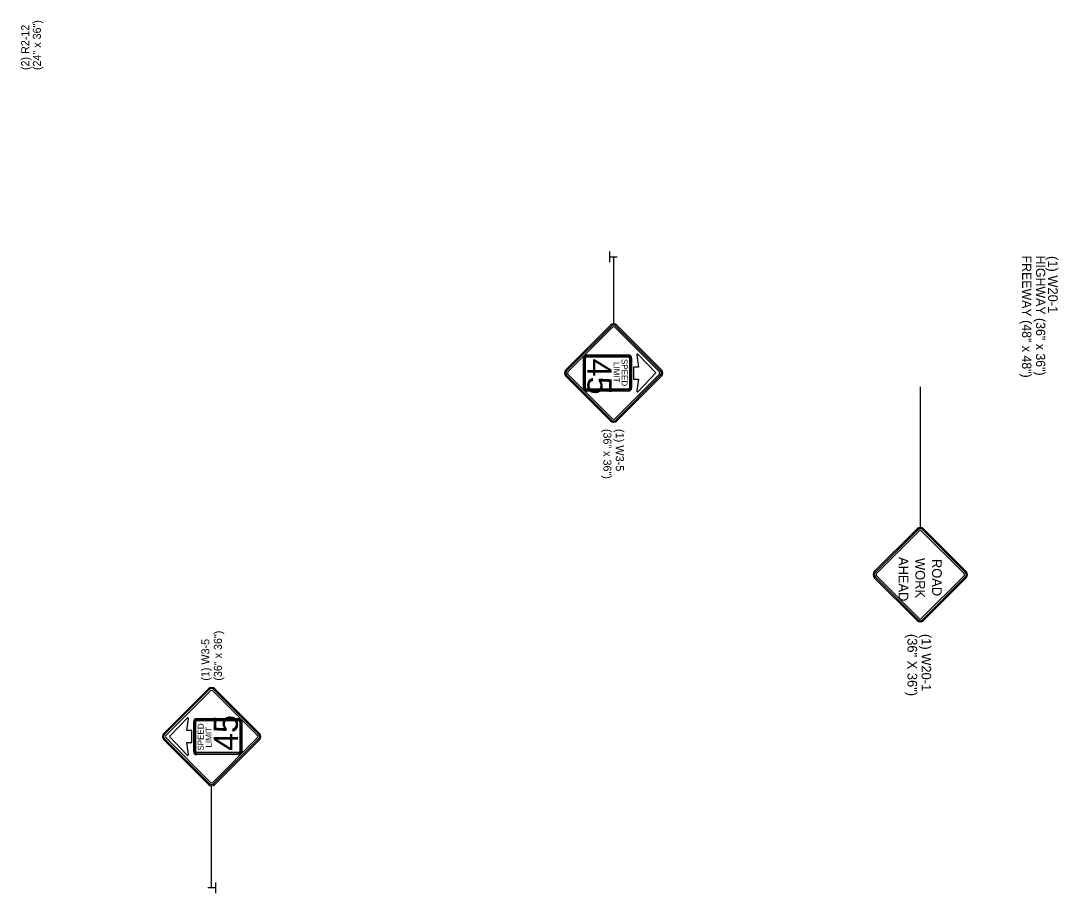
# Model space of a CAD drawing. Extents: x 1930579 to 1934718, y 596452 to 597844.
# Drawn here: x 1931414 to 1932190, y 596916 to 597568 of the extents above; entities that cross this region are included whole.
import ezdxf

# ---------------------------------------------------------------- set-up
doc = ezdxf.new("R2010")
doc.units = 0
for name, color, linetype in [('Default', 7, 'Continuous'), ('P_TC_Signs_Permanent', 7, 'Continuous'), ('P_TC_Signs_Temporary', 7, 'Continuous'), ('R_Annotation', 7, 'Continuous')]:
    doc.layers.add(name, color=color, linetype=linetype)

msp = doc.modelspace()

# ---------------------------------------------------------------- linework, layer by layer
at = {"layer": 'Default'}
for p, q in [((1931854.54, 597387.42), (1931854.54, 597395.42)), ((1931854.66, 597391.4), (1931860.12, 597391.4)), ((1931559.69, 596919.8), (1931554.22, 596919.8)), ((1931559.81, 596923.78), (1931559.81, 596915.77))]:
    msp.add_line(p, q, dxfattribs=at)
at = {"layer": 'P_TC_Signs_Permanent'}
for p, q in [((1931855, 597340.43), (1931821.59, 597307.02)), ((1931855.66, 597339.77), (1931822.25, 597306.36)), ((1931856.59, 597338.84), (1931823.18, 597305.43)), ((1931891.59, 597305.43), (1931858.18, 597338.84)), ((1931892.52, 597306.36), (1931859.11, 597339.77)), ((1931893.19, 597307.02), (1931859.77, 597340.43)), ((1931834.8, 597293.53), (1931834.8, 597315.73)), ((1931837.2, 597318.13), (1931868.4, 597318.13)), ((1931870.8, 597315.73), (1931870.8, 597293.53)), ((1931821.59, 597302.25), (1931855, 597268.83)), ((1931822.25, 597302.91), (1931855.66, 597269.5)), ((1931823.18, 597303.84), (1931856.59, 597270.43)), ((1931858.18, 597270.43), (1931891.59, 597303.84)), ((1931859.11, 597269.5), (1931892.52, 597302.91)), ((1931859.77, 597268.83), (1931893.19, 597302.25)), ((1931868.4, 597291.13), (1931837.2, 597291.13)), ((1931554.57, 597068.67), (1931521.16, 597035.26)), ((1931555.23, 597068.01), (1931521.82, 597034.6)), ((1931556.16, 597067.08), (1931522.75, 597033.67)), ((1931591.16, 597033.67), (1931557.75, 597067.08)), ((1931592.09, 597034.6), (1931558.68, 597068.01)), ((1931592.75, 597035.26), (1931559.34, 597068.67)), ((1931543.55, 597021.77), (1931543.55, 597043.97)), ((1931545.95, 597046.37), (1931577.15, 597046.37)), ((1931579.55, 597043.97), (1931579.55, 597021.77)), ((1931521.16, 597030.49), (1931554.57, 596997.07)), ((1931521.82, 597031.15), (1931555.23, 596997.74)), ((1931522.75, 597032.08), (1931556.16, 596998.67)), ((1931557.75, 596998.67), (1931591.16, 597032.08)), ((1931558.68, 596997.74), (1931592.09, 597031.15)), ((1931559.34, 596997.07), (1931592.75, 597030.49)), ((1931577.15, 597019.37), (1931545.95, 597019.37))]:
    msp.add_line(p, q, dxfattribs=at)
for points in [[(1931835.4, 597315.73), (1931835.4, 597293.53)], [(1931836.3, 597293.53), (1931836.3, 597315.73)], [(1931868.4, 597317.53), (1931837.2, 597317.53)], [(1931837.2, 597316.63), (1931868.4, 597316.63)], [(1931869.3, 597315.73), (1931869.3, 597304.63), (1931869.3, 597293.53)], [(1931870.2, 597293.53), (1931870.2, 597304.63), (1931870.2, 597315.73)], [(1931874.74, 597318.09), (1931875.86, 597309.13), (1931872.3, 597309.13), (1931872.3, 597300.13), (1931875.85, 597300.13), (1931874.74, 597291.24)], [(1931875.71, 597290.79), (1931888.8, 597304.67), (1931875.71, 597318.55)], [(1931868.4, 597292.63), (1931837.2, 597292.63)], [(1931837.2, 597291.73), (1931868.4, 597291.73)], [(1931538.64, 597046.72), (1931525.55, 597032.84), (1931538.64, 597018.96)], [(1931539.6, 597019.41), (1931538.48, 597028.37), (1931542.05, 597028.37), (1931542.05, 597037.37), (1931538.49, 597037.37), (1931539.6, 597046.26)], [(1931544.15, 597043.97), (1931544.15, 597032.87), (1931544.15, 597021.77)], [(1931545.05, 597021.77), (1931545.05, 597032.87), (1931545.05, 597043.97)], [(1931577.15, 597045.77), (1931545.95, 597045.77)], [(1931545.95, 597044.87), (1931577.15, 597044.87)], [(1931578.05, 597043.97), (1931578.05, 597021.77)], [(1931578.95, 597021.77), (1931578.95, 597043.97)], [(1931577.15, 597020.87), (1931545.95, 597020.87)], [(1931545.95, 597019.97), (1931577.15, 597019.97)]]:
    msp.add_lwpolyline(points, dxfattribs=at)
for centre, radius, start, end in [((1931857.39, 597338.04), 3.38, 45, 135), ((1931857.39, 597338.04), 2.44, 45, 135), ((1931857.39, 597338.04), 1.13, 45, 135), ((1931837.2, 597315.73), 2.4, 90, 180), ((1931837.2, 597315.73), 1.8, 90, 180), ((1931837.2, 597315.73), 0.9, 90, 180), ((1931868.4, 597315.73), 2.4, 360, 90), ((1931868.4, 597315.73), 1.8, 360, 90), ((1931868.4, 597315.73), 0.9, 360, 90), ((1931875.3, 597318.16), 0.563, 43.31166, 187.12501), ((1931823.98, 597304.63), 3.38, 135, 225), ((1931823.98, 597304.63), 2.44, 135, 225), ((1931823.98, 597304.63), 1.13, 135, 225), ((1931890.8, 597304.63), 1.13, 315, 45), ((1931890.8, 597304.63), 2.44, 315, 45), ((1931890.8, 597304.63), 3.38, 315, 45), ((1931837.2, 597293.53), 2.4, 180, 270), ((1931837.2, 597293.53), 1.8, 180, 270), ((1931837.2, 597293.53), 0.9, 180, 270), ((1931868.4, 597293.53), 2.4, 270, 360), ((1931868.4, 597293.53), 1.8, 270, 360), ((1931868.4, 597293.53), 0.9, 270, 360), ((1931875.3, 597291.17), 0.563, 172.87498, 316.68834), ((1931857.39, 597271.22), 3.38, 225, 315), ((1931857.39, 597271.22), 2.44, 225, 315), ((1931857.39, 597271.22), 1.13, 225, 315), ((1931556.96, 597066.28), 3.38, 45, 135), ((1931556.96, 597066.28), 2.44, 45, 135), ((1931556.96, 597066.28), 1.13, 45, 135), ((1931539.05, 597046.33), 0.563, 352.87498, 136.68834), ((1931545.95, 597043.97), 2.4, 90, 180), ((1931545.95, 597043.97), 1.8, 90, 180), ((1931545.95, 597043.97), 0.9, 90, 180), ((1931577.15, 597043.97), 2.4, 360, 90), ((1931577.15, 597043.97), 1.8, 360, 90), ((1931577.15, 597043.97), 0.9, 360, 90), ((1931523.55, 597032.87), 3.38, 135, 225), ((1931523.55, 597032.87), 2.44, 135, 225), ((1931590.37, 597032.87), 2.44, 315, 45), ((1931590.37, 597032.87), 3.38, 315, 45), ((1931523.55, 597032.87), 1.13, 135, 225), ((1931590.37, 597032.87), 1.13, 315, 45), ((1931539.05, 597019.34), 0.563, 223.31166, 7.12501), ((1931545.95, 597021.77), 2.4, 180, 270), ((1931545.95, 597021.77), 1.8, 180, 270), ((1931545.95, 597021.77), 0.9, 180, 270), ((1931577.15, 597021.77), 2.4, 270, 360), ((1931577.15, 597021.77), 1.8, 270, 360), ((1931577.15, 597021.77), 0.9, 270, 360), ((1931556.96, 596999.46), 3.38, 225, 315), ((1931556.96, 596999.46), 2.44, 225, 315), ((1931556.96, 596999.46), 1.13, 225, 315)]:
    msp.add_arc(centre, radius, start, end, dxfattribs=at)
at = {"layer": 'P_TC_Signs_Temporary'}
for p, q in [((1932052.17, 597156.19), (1932084.25, 597188.27)), ((1932052.81, 597155.55), (1932084.88, 597187.63)), ((1932053.7, 597154.66), (1932085.77, 597186.74)), ((1932087.3, 597186.74), (1932119.38, 597154.66)), ((1932088.19, 597187.63), (1932120.27, 597155.55)), ((1932088.83, 597188.27), (1932120.9, 597156.19)), ((1932084.25, 597119.53), (1932052.17, 597151.61)), ((1932084.88, 597120.17), (1932052.81, 597152.25)), ((1932085.77, 597121.06), (1932053.7, 597153.14)), ((1932119.38, 597153.14), (1932087.3, 597121.06)), ((1932120.27, 597152.25), (1932088.19, 597120.17)), ((1932120.9, 597151.61), (1932088.83, 597119.53))]:
    msp.add_line(p, q, dxfattribs=at)
for centre, radius, start, end in [((1932086.54, 597185.97), 3.24, 45, 135), ((1932086.54, 597185.97), 2.34, 45, 135), ((1932086.54, 597185.97), 1.08, 45, 135), ((1932054.46, 597153.9), 3.24, 135, 225), ((1932054.46, 597153.9), 2.34, 135, 225), ((1932054.46, 597153.9), 1.08, 135, 225), ((1932118.61, 597153.9), 1.08, 315, 45), ((1932118.61, 597153.9), 2.34, 315, 45), ((1932118.61, 597153.9), 3.24, 315, 45), ((1932086.54, 597121.83), 3.24, 225, 315), ((1932086.54, 597121.83), 2.34, 225, 315), ((1932086.54, 597121.83), 1.08, 225, 315)]:
    msp.add_arc(centre, radius, start, end, dxfattribs=at)
at = {"layer": 'R_Annotation'}
for p, q in [((1931857.39, 597391.4), (1931857.39, 597341.42)), ((1932086.54, 597294.42), (1932086.54, 597189.21)), ((1932086.54, 597294.42), (1932086.54, 597189.21)), ((1931556.96, 596919.8), (1931556.96, 596996.09))]:
    msp.add_line(p, q, dxfattribs=at)

# ---------------------------------------------------------------- texts
at = {"layer": 'P_TC_Signs_Permanent'}
for s, height, rotation, p in [('45', 18, 270, (1931837.8, 597315.31)), ('SPEED', 4.5, 270, (1931863.3, 597315.13)), ('LIMIT', 4.5, 270, (1931857.3, 597312.82)), ('SPEED', 4.5, 90, (1931551.05, 597022.37)), ('45', 18, 90, (1931576.55, 597022.19)), ('LIMIT', 4.5, 90, (1931557.05, 597024.68))]:
    msp.add_text(s, height=height, rotation=rotation, dxfattribs=at).set_placement(p)
at = {"layer": 'P_TC_Signs_Temporary'}
for s, p in [(' AHEAD ', (1932070.38, 597169.78)), ('WORK', (1932082.88, 597166.37)), (' ROAD ', (1932095.38, 597168.32))]:
    msp.add_text(s, height=7.2, rotation=270, dxfattribs=at).set_placement(p)
at = {"layer": 'R_Annotation'}
for s, height, rotation, p in [('(2) R2-12', 6, 90, (1931420.63, 597531.09)), ('(24" x 36")', 5.9996, 90, (1931429.38, 597531.09)), ('FREEWAY (48" x 48")', 6.912, 270, (1932162.66, 597392.45)), ('HIGHWAY (36" x 36")', 6.912, 270, (1932173.03, 597392.45)), ('(1) W20-1', 7.2, 270, (1932182.05, 597392.09)), ('(36" x 36")', 5.9996, 270, (1931849.71, 597262.85)), ('(1) W3-5', 6.1, 270, (1931858.97, 597262.85)), ('(36" x 36")', 6, 90, (1931564.64, 597074.66)), ('(1) W3-5', 6, 90, (1931555.28, 597074.66)), ('(36" X 36")', 7.2, 270, (1932076.97, 597109.59)), ('(1) W20-1', 7.2, 270, (1932087.45, 597109.59))]:
    msp.add_text(s, height=height, rotation=rotation, dxfattribs=at).set_placement(p)

doc.saveas('drawing.dxf')
